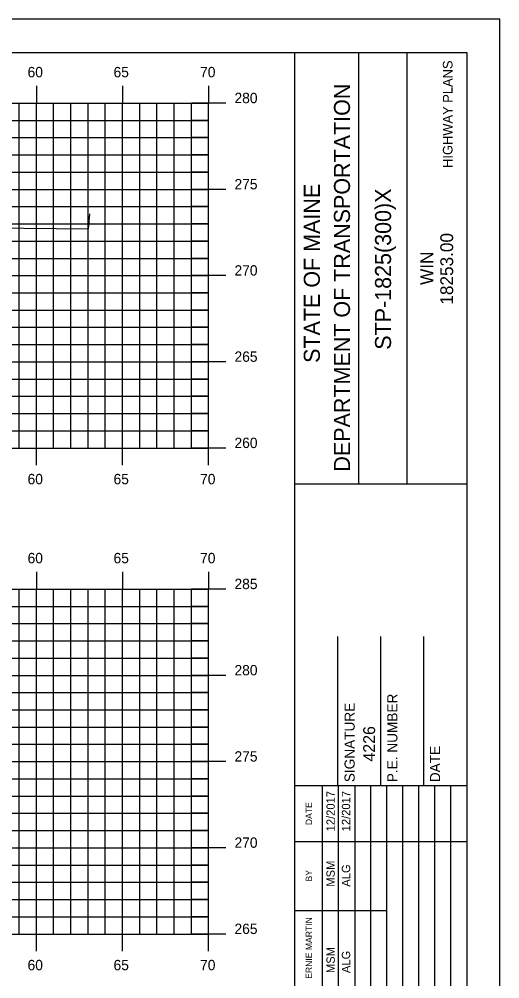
# Model space of a CAD drawing. Extents: x 854676 to 854846, y 366268 to 366378.
# Drawn here: x 854818.1 to 854846, y 366322.5 to 366378.2 of the extents above; entities that cross this region are included whole.
import ezdxf

# ---------------------------------------------------------------- set-up
doc = ezdxf.new("R2010")
doc.units = 0
for name, color, linetype in [('ANNOTATION', 7, 'Continuous'), ('BORDER', 7, 'Continuous'), ('H_V ANNOTATION', 7, 'Continuous'), ('HIGHWAY_TITLE', 7, 'Continuous'), ('MAJOR', 7, 'Continuous'), ('MINOR', 7, 'Continuous'), ('PLOT BOUNDARY', 7, 'Continuous'), ('S_Roadway_Centerline', 7, 'Continuous')]:
    doc.layers.add(name, color=color, linetype=linetype)

msp = doc.modelspace()

# ---------------------------------------------------------------- linework, layer by layer
at = {"layer": 'BORDER'}
for p, q in [((854844.107, 366376.236), (854684.107, 366376.236)), ((854834.107, 366271.236), (854834.107, 366376.239)), ((854837.835, 366351.234), (854837.835, 366376.234)), ((854840.63, 366351.234), (854840.63, 366376.234)), ((854844.107, 366271.236), (854844.107, 366376.236)), ((854834.107, 366351.231), (854844.107, 366351.231)), ((854836.607, 366333.739), (854836.607, 366342.387)), ((854839.107, 366333.739), (854839.107, 366342.387)), ((854841.607, 366333.739), (854841.607, 366342.387)), ((854834.107, 366333.739), (854844.107, 366333.739))]:
    msp.add_line(p, q, dxfattribs=at)
for points in [[(854835.721, 366330.489), (854835.721, 366333.739)], [(854836.654, 366316.242), (854836.654, 366333.739)], [(854837.586, 366333.739), (854837.586, 366316.242)], [(854838.517, 366316.242), (854838.517, 366333.739)], [(854839.449, 366316.242), (854839.449, 366333.739)], [(854840.381, 366316.242), (854840.381, 366333.739)], [(854841.312, 366316.242), (854841.312, 366333.739)], [(854842.244, 366316.242), (854842.244, 366333.739)], [(854843.176, 366316.242), (854843.176, 366333.739)], [(854835.722, 366316.242), (854835.722, 366333.033)], [(854834.107, 366330.489), (854844.107, 366330.489)], [(854834.107, 366326.489), (854835.722, 366326.489)], [(854835.721, 366326.489), (854839.448, 366326.489)]]:
    msp.add_lwpolyline(points, dxfattribs=at)
at = {"layer": 'MAJOR'}
for p, q in [((854819.106, 366374.311), (854819.106, 366373.309)), ((854824.106, 366374.311), (854824.106, 366373.309)), ((854829.106, 366374.311), (854829.106, 366373.309)), ((854689.106, 366373.309), (854829.106, 366373.309)), ((854689.106, 366373.309), (854829.106, 366373.309)), ((854819.106, 366353.309), (854819.106, 366373.309)), ((854824.106, 366353.309), (854824.106, 366373.309)), ((854830.108, 366373.309), (854828.104, 366373.309)), ((854829.106, 366353.309), (854829.106, 366373.309)), ((854829.106, 366353.309), (854829.106, 366373.309)), ((854689.106, 366368.309), (854829.106, 366368.309)), ((854830.108, 366368.309), (854828.104, 366368.309)), ((854689.106, 366363.309), (854829.106, 366363.309)), ((854830.108, 366363.309), (854828.104, 366363.309)), ((854689.106, 366358.309), (854829.106, 366358.309)), ((854830.108, 366358.309), (854828.104, 366358.309)), ((854689.106, 366353.309), (854829.106, 366353.309)), ((854689.106, 366353.309), (854829.106, 366353.309)), ((854819.106, 366352.307), (854819.106, 366353.309)), ((854824.106, 366352.307), (854824.106, 366353.309)), ((854830.108, 366353.309), (854828.104, 366353.309)), ((854829.106, 366352.307), (854829.106, 366353.309)), ((854819.106, 366346.13), (854819.106, 366345.128)), ((854824.106, 366346.13), (854824.106, 366345.128)), ((854829.106, 366346.13), (854829.106, 366345.128)), ((854689.106, 366345.128), (854829.106, 366345.128)), ((854689.106, 366345.128), (854829.106, 366345.128)), ((854819.106, 366325.128), (854819.106, 366345.128)), ((854824.106, 366325.128), (854824.106, 366345.128)), ((854830.108, 366345.128), (854828.104, 366345.128)), ((854829.106, 366325.128), (854829.106, 366345.128)), ((854829.106, 366325.128), (854829.106, 366345.128)), ((854689.106, 366340.128), (854829.106, 366340.128)), ((854830.108, 366340.128), (854828.104, 366340.128)), ((854689.106, 366335.128), (854829.106, 366335.128)), ((854830.108, 366335.128), (854828.104, 366335.128)), ((854689.106, 366330.128), (854829.106, 366330.128)), ((854830.108, 366330.128), (854828.104, 366330.128)), ((854689.106, 366325.128), (854829.106, 366325.128)), ((854689.106, 366325.128), (854829.106, 366325.128)), ((854819.106, 366324.126), (854819.106, 366325.128)), ((854824.106, 366324.126), (854824.106, 366325.128)), ((854830.108, 366325.128), (854828.104, 366325.128)), ((854829.106, 366324.126), (854829.106, 366325.128))]:
    msp.add_line(p, q, dxfattribs=at)
at = {"layer": 'MINOR'}
for p, q in [((854818.106, 366353.309), (854818.106, 366373.309)), ((854820.106, 366353.309), (854820.106, 366373.309)), ((854821.106, 366353.309), (854821.106, 366373.309)), ((854822.106, 366353.309), (854822.106, 366373.309)), ((854823.106, 366353.309), (854823.106, 366373.309)), ((854825.106, 366353.309), (854825.106, 366373.309)), ((854826.106, 366353.309), (854826.106, 366373.309)), ((854827.106, 366353.309), (854827.106, 366373.309)), ((854828.106, 366353.309), (854828.106, 366373.309)), ((854689.106, 366372.309), (854829.106, 366372.309)), ((854829.106, 366372.309), (854828.104, 366372.309)), ((854689.106, 366371.309), (854829.106, 366371.309)), ((854829.106, 366371.309), (854828.104, 366371.309)), ((854689.106, 366370.309), (854829.106, 366370.309)), ((854829.106, 366370.309), (854828.104, 366370.309)), ((854689.106, 366369.309), (854829.106, 366369.309)), ((854829.106, 366369.309), (854828.104, 366369.309)), ((854689.106, 366367.309), (854829.106, 366367.309)), ((854829.106, 366367.309), (854828.104, 366367.309)), ((854689.106, 366366.309), (854829.106, 366366.309)), ((854829.106, 366366.309), (854828.104, 366366.309)), ((854689.106, 366365.309), (854829.106, 366365.309)), ((854829.106, 366365.309), (854828.104, 366365.309)), ((854689.106, 366364.309), (854829.106, 366364.309)), ((854829.106, 366364.309), (854828.104, 366364.309)), ((854689.106, 366362.309), (854829.106, 366362.309)), ((854829.106, 366362.309), (854828.104, 366362.309)), ((854689.106, 366361.309), (854829.106, 366361.309)), ((854829.106, 366361.309), (854828.104, 366361.309)), ((854689.106, 366360.309), (854829.106, 366360.309)), ((854829.106, 366360.309), (854828.104, 366360.309)), ((854689.106, 366359.309), (854829.106, 366359.309)), ((854829.106, 366359.309), (854828.104, 366359.309)), ((854689.106, 366357.309), (854829.106, 366357.309)), ((854829.106, 366357.309), (854828.104, 366357.309)), ((854689.106, 366356.309), (854829.106, 366356.309)), ((854829.106, 366356.309), (854828.104, 366356.309)), ((854689.106, 366355.309), (854829.106, 366355.309)), ((854829.106, 366355.309), (854828.104, 366355.309)), ((854689.106, 366354.309), (854829.106, 366354.309)), ((854829.106, 366354.309), (854828.104, 366354.309)), ((854818.106, 366325.128), (854818.106, 366345.128)), ((854820.106, 366325.128), (854820.106, 366345.128)), ((854821.106, 366325.128), (854821.106, 366345.128)), ((854822.106, 366325.128), (854822.106, 366345.128)), ((854823.106, 366325.128), (854823.106, 366345.128)), ((854825.106, 366325.128), (854825.106, 366345.128)), ((854826.106, 366325.128), (854826.106, 366345.128)), ((854827.106, 366325.128), (854827.106, 366345.128)), ((854828.106, 366325.128), (854828.106, 366345.128)), ((854689.106, 366344.128), (854829.106, 366344.128)), ((854829.106, 366344.128), (854828.104, 366344.128)), ((854689.106, 366343.128), (854829.106, 366343.128)), ((854829.106, 366343.128), (854828.104, 366343.128)), ((854689.106, 366342.128), (854829.106, 366342.128)), ((854829.106, 366342.128), (854828.104, 366342.128)), ((854689.106, 366341.128), (854829.106, 366341.128)), ((854829.106, 366341.128), (854828.104, 366341.128)), ((854689.106, 366339.128), (854829.106, 366339.128)), ((854829.106, 366339.128), (854828.104, 366339.128)), ((854689.106, 366338.128), (854829.106, 366338.128)), ((854829.106, 366338.128), (854828.104, 366338.128)), ((854689.106, 366337.128), (854829.106, 366337.128)), ((854829.106, 366337.128), (854828.104, 366337.128)), ((854689.106, 366336.128), (854829.106, 366336.128)), ((854829.106, 366336.128), (854828.104, 366336.128)), ((854689.106, 366334.128), (854829.106, 366334.128)), ((854829.106, 366334.128), (854828.104, 366334.128)), ((854689.106, 366333.128), (854829.106, 366333.128)), ((854829.106, 366333.128), (854828.104, 366333.128)), ((854689.106, 366332.128), (854829.106, 366332.128)), ((854829.106, 366332.128), (854828.104, 366332.128)), ((854689.106, 366331.128), (854829.106, 366331.128)), ((854829.106, 366331.128), (854828.104, 366331.128)), ((854689.106, 366329.128), (854829.106, 366329.128)), ((854829.106, 366329.128), (854828.104, 366329.128)), ((854689.106, 366328.128), (854829.106, 366328.128)), ((854829.106, 366328.128), (854828.104, 366328.128)), ((854689.106, 366327.128), (854829.106, 366327.128)), ((854829.106, 366327.128), (854828.104, 366327.128)), ((854689.106, 366326.128), (854829.106, 366326.128)), ((854829.106, 366326.128), (854828.104, 366326.128))]:
    msp.add_line(p, q, dxfattribs=at)
at = {"layer": 'PLOT BOUNDARY'}
msp.add_lwpolyline([(854676.013, 366268.177), (854846.013, 366268.177), (854846.013, 366378.177), (854676.013, 366378.177)], close=True, dxfattribs=at)
at = {"layer": 'S_Roadway_Centerline'}
msp.add_lwpolyline([(854760.071, 366365.226), (854771.088, 366364.995), (854777.534, 366364.686), (854778.369, 366364.622), (854778.629, 366364.634), (854779.762, 366364.729), (854780.446, 366364.709), (854781.576, 366364.775), (854785.006, 366365.003), (854787.636, 366365.067), (854790.678, 366365.23), (854793.359, 366365.326), (854798.518, 366365.484), (854799.286, 366365.525), (854800.647, 366365.62), (854803.663, 366365.778), (854804.946, 366365.832), (854807.983, 366365.97), (854814.583, 366366.102), (854822.139, 366366.02), (854822.216, 366366.887)], dxfattribs=at)

# ---------------------------------------------------------------- texts
at = {"layer": 'ANNOTATION'}
msp.add_text('4226', height=0.69, rotation=90, dxfattribs=at).set_placement((854838.771, 366335.13))
at = {"layer": 'BORDER'}
for s, height, p in [('DEPARTMENT OF TRANSPORTATION', 0.93176, (854837.313, 366351.942)), ('STATE OF MAINE', 0.93176, (854835.562, 366358.248)), ('STP-1825(300)X', 0.93176, (854839.698, 366359.008)), ('18253.00', 0.7453, (854843.302, 366361.623)), ('WIN', 0.7453, (854842.143, 366362.766)), ('P.E. NUMBER', 0.59055, (854840.067, 366333.932)), ('SIGNATURE', 0.5906, (854837.587, 366333.932)), ('DATE', 0.5906, (854842.548, 366333.932)), ('12/2017', 0.4845, (854836.429, 366331.081)), ('12/2017', 0.4845, (854837.324, 366331.081)), ('DATE', 0.3714, (854835.111, 366331.445)), ('MSM', 0.4845, (854836.429, 366327.872)), ('ALG', 0.4845, (854837.324, 366327.872)), ('BY', 0.3714, (854835.111, 366328.174)), ('ERNIE MARTIN', 0.37275, (854835.111, 366322.531)), ('MSM', 0.4845, (854836.429, 366322.863)), ('ALG', 0.4845, (854837.324, 366322.863))]:
    msp.add_text(s, height=height, rotation=90, dxfattribs=at).set_placement(p)
at = {"layer": 'H_V ANNOTATION'}
for s, p in [('60', (854818.592, 366374.809)), ('65', (854823.584, 366374.809)), ('70', (854828.608, 366374.809)), ('280', (854830.606, 366373.309)), ('275', (854830.606, 366368.309)), ('270', (854830.606, 366363.309)), ('265', (854830.606, 366358.309)), ('260', (854830.606, 366353.309)), ('60', (854818.592, 366351.209)), ('65', (854823.584, 366351.209)), ('70', (854828.608, 366351.209)), ('60', (854818.592, 366346.628)), ('65', (854823.584, 366346.628)), ('70', (854828.608, 366346.628)), ('285', (854830.606, 366345.128)), ('280', (854830.606, 366340.128)), ('275', (854830.606, 366335.128)), ('270', (854830.606, 366330.128)), ('265', (854830.606, 366325.128)), ('60', (854818.592, 366323.028)), ('65', (854823.584, 366323.028)), ('70', (854828.608, 366323.028))]:
    msp.add_text(s, height=0.6, dxfattribs=at).set_placement(p)
at = {"layer": 'HIGHWAY_TITLE'}
msp.add_text('HIGHWAY PLANS', height=0.55901, rotation=90, dxfattribs=at).set_placement((854843.265, 366369.552))

doc.saveas('drawing.dxf')
